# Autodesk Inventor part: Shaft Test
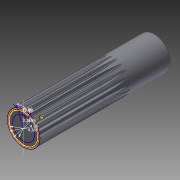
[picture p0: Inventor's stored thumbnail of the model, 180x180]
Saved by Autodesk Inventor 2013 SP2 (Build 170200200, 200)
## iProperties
Created: 2020-02
Part Number: Shaft Test
Material: Steel
Document SubType Name: Modeling
Designer: DELL
Density: 1 g/cm^3
CustomPartVersion: 1
Author: DELL
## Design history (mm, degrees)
sketch "Sketch3"
  geometry: C1 r 2.5 at (0, 0); 1 further point
  constraints: 1 centre point, 1 coincident
  dimensions: "d16" = 5 diameter of C1
extrude "Extrusion1" new body sketch "Sketch3" distance "d18" = 20; taper "d19" = 0 deg
chamfer "Chamfer4" distance "d21" = 0.25; stored, may be unused: second distance "d22" = 2, angle "d23" = 45 deg
node "Involute Splining8"
sketch "Sketch4" dims "d21" = 0.25
  geometry: L1 (0, 0)-(1.12, 2.704); L2 (0, -3.533)-(0, 3.875) reference; L3 (0, 0)-(-1.12, 2.704); L4 (0.643, 1.552)-(-1.571, 2.469); C1 r 2.375 at (0, 0); C2 r 2.475 at (0, 0); C3 r 2.183 at (0, 0); C4 r 1.68 at (0, 0); 1 further point
  constraints: 6 end point, 4 centre point, 4 coincident, 1 perpendicular, 1 point on line, 1 tangent
  dimensions: "d46" = 4.75 diameter of C1; "d48" = 4.95 diameter of C2; "d49" = 4.367 diameter of C3; "d50" = 3.359 diameter of C4; "d52" = 22.5 deg angle of L1 L2; "d53" = 45 deg angle of L1 L3
sketch "Sketch5"
  geometry: L1 (0, -1.686)-(-0.333, -2.668); L2 (0, -1.686)-(0.336, -2.675); L3 (0, -3.753)-(0, 3.78) reference; 5 further points
  constraints: 4 end point, 2 other
  dimensions: "d54" = 1.6862 distance of L1.start point (0, 0); "d55" = 18.75 deg angle of L2 L3; "d56" = 18.75 deg angle of L3 L1 (= d55); "d57" = 37.5 deg angle of L2 L1 (derived)
body "Solid2"
feature "Shaft Groove"
